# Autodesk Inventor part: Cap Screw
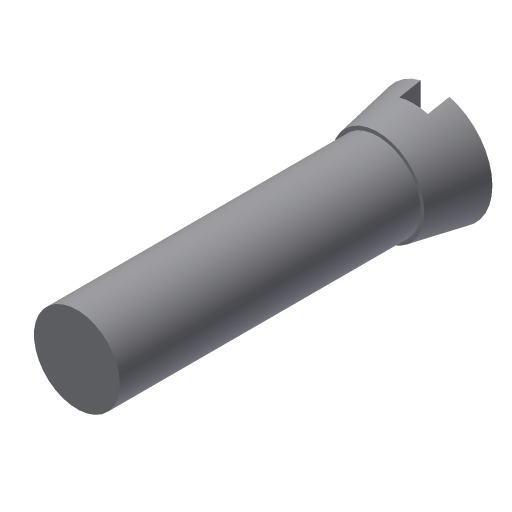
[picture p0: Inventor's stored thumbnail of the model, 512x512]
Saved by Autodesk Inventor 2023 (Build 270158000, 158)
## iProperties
Shininess: 77.0
Length Units: 11269
Angle Units: 11279
Time Units: 11290
Mass Units: 11283
Length Display Precision: 3
Angle Display Precision: 2
Created: 2002-02
Part Number: Cap Screw
Document SubType Name: Modeling
Designer: ***
Density: 1 g/cm^3
Material: Generic
Appearance: Default
Density: 0.0
Volumn: 0.0
Area: 0.0
PropertySet Name: Model Information
Control State: 0
Master: False
Checked Out: False
Author: ***
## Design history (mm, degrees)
sketch "Sketch1"
  geometry: L1 (0, 27.83)-(4, 27.83); L2 (4, 27.83)-(3.25, 23.83); L3 (3.25, 23.83)-(0, 23.83); L4 (0, 23.83)-(0, 27.83)
  constraints: 8 end point, 1 horizontal, 1 parallel, 1 perpendicular, 1 point on line
  dimensions: "d2" = 4 distance from line of L1 L2.end; "d5" = 8 diameter of L1.end L4; "d6" = 6.5 diameter of L3.start L4; "d14" = 4 distance of L3.end L1.start
revolve "Revolution1" sketch "Sketch1" stored, may be unused: angle "d7" = 90 deg
sketch "Sketch2"
  geometry: C1 r 3 at (0, 0)
  constraints: 1 centre point
  dimensions: "d8" = 6 diameter of C1
extrude "Extrusion1" join sketch "Sketch2" distance "d9" = 21; taper "d10" = 0 deg
sketch "Sketch3"
  geometry: L1 (-1, 28.967)-(1, 28.967); L2 (1, 28.967)-(1, 26.33); L3 (1, 26.33)-(-1, 26.33); L4 (-1, 26.33)-(-1, 28.967); L5 (-4, 27.83)-(4, 27.83) reference
  constraints: 8 end point, 2 parallel, 1 horizontal, 1 perpendicular
  dimensions: "d11" = 2 distance of L1.start L1.end; "d15" = 1.5 distance between parallel lines of L5 L3
extrude "Extrusion2" cut sketch "Sketch3" extent not by distance; stored distance "d12" = 24; taper "d13" = 0 deg
body "Solid1"
